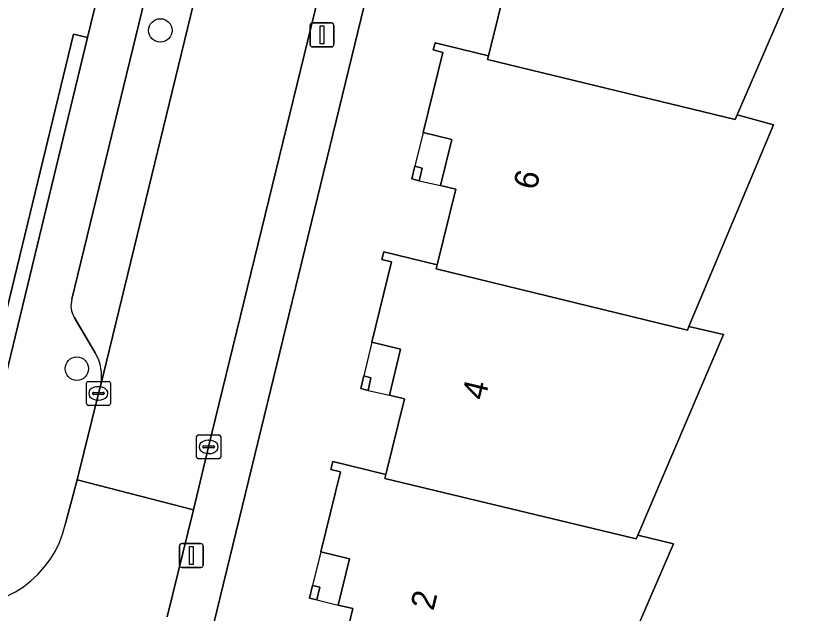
# Model space of a CAD drawing. Extents: x 163266 to 164362, y 381528 to 382286.
# Drawn here: x 164033.14 to 164065.88, y 382076.29 to 382101.22 of the extents above; entities that cross this region are included whole.
import ezdxf

# ---------------------------------------------------------------- set-up
doc = ezdxf.new("R2010")
doc.units = 0
for name, color, linetype in [('IMGEO_Boom', 7, 'Continuous'), ('IMGEO_Erf', 7, 'Continuous'), ('IMGEO_Groenvoorziening', 7, 'Continuous'), ('IMGEO_Haag', 7, 'Continuous'), ('IMGEO_Kolk', 7, 'Continuous'), ('IMGEO_Lichtmast', 7, 'Continuous'), ('IMGEO_Pand', 7, 'Continuous'), ('IMGEO_Pand_nummerreeks', 7, 'Continuous'), ('IMGEO_Pand_overbouw', 7, 'Continuous'), ('IMGEO_Parkeervlak_open', 7, 'Continuous'), ('IMGEO_Rijbaan_lokaal_open', 7, 'Continuous'), ('IMGEO_Voetpad_open', 7, 'Continuous')]:
    doc.layers.add(name, color=color, linetype=linetype)

msp = doc.modelspace()

# ---------------------------------------------------------------- linework, layer by layer
at = {"layer": 'IMGEO_Boom'}
for centre in [(164039.169, 382100.607), (164035.69, 382086.497)]:
    msp.add_circle(centre, 0.489, dxfattribs=at)
at = {"layer": 'IMGEO_Erf'}
for points in [[(164055.615, 382134.307), (164041.028, 382074.335), (164056.155, 382068.998), (164066.938, 382065.194), (164076.002, 382063.011), (164076.035, 382063.211), (164076.111, 382063.521), (164077.023, 382063.297), (164078.096, 382067.688), (164077.183, 382067.911), (164078.503, 382073.312), (164079.825, 382078.723), (164080.737, 382078.499), (164081.848, 382083.048), (164082.961, 382087.602), (164082.048, 382087.825), (164083.378, 382093.267), (164084.719, 382098.754), (164085.631, 382098.53), (164086.738, 382103.06)], [(164066.802, 382105.412), (164063.201, 382097.083), (164064.72, 382096.672), (164061.198, 382088.256), (164062.634, 382087.923), (164059.062, 382079.546), (164060.552, 382079.184), (164056.298, 382069.343), (164052.914, 382070.819)], [(164046.358, 382073.031), (164047.197, 382076.489), (164046.586, 382076.638), (164047.052, 382078.561), (164045.858, 382078.851), (164046.672, 382082.193), (164046.275, 382082.296), (164046.362, 382082.629), (164048.565, 382082.088), (164049.347, 382085.239), (164048.716, 382085.391), (164049.178, 382087.314), (164047.988, 382087.606), (164048.802, 382090.948), (164048.405, 382091.051), (164048.489, 382091.372), (164050.7, 382090.829), (164051.482, 382093.98), (164050.851, 382094.132), (164051.313, 382096.055), (164050.123, 382096.347), (164050.937, 382099.689), (164050.54, 382099.792), (164050.618, 382100.093), (164052.842, 382099.547), (164053.625, 382102.698)]]:
    msp.add_lwpolyline(points, dxfattribs=at)
for points in [[(164049.959, 382094.336), (164049.654, 382094.411), (164049.774, 382094.938), (164050.079, 382094.863)], [(164047.523, 382085.667), (164047.643, 382086.194), (164047.948, 382086.119), (164047.828, 382085.592)], [(164045.695, 382076.855), (164045.39, 382076.93), (164045.51, 382077.457), (164045.815, 382077.382)]]:
    msp.add_lwpolyline(points, close=True, dxfattribs=at)
at = {"layer": 'IMGEO_Groenvoorziening'}
msp.add_lwpolyline([(164022.886, 382088.082), (164031.276, 382082.812), (164035.554, 382100.455), (164036.138, 382100.312), (164036.608, 382102.251), (164036.024, 382102.399), (164042.415, 382128.743), (164042.999, 382128.602), (164046.57, 382143.324), (164043.085, 382144.179), (164040.57, 382144.799), (164040.399, 382144.108), (164040.29, 382143.669), (164044.324, 382142.632), (164041.179, 382131.271)], dxfattribs=at)
msp.add_lwpolyline([(164036.138, 382100.312), (164035.554, 382100.455), (164031.276, 382082.812), (164031.812, 382082.475)], close=True, dxfattribs=at)
at = {"layer": 'IMGEO_Haag'}
msp.add_lwpolyline([(164036.138, 382100.312), (164035.554, 382100.455), (164031.276, 382082.812), (164031.812, 382082.475)], close=True, dxfattribs=at)
at = {"layer": 'IMGEO_Kolk'}
for p, q in [((164036.086, 382085.04), (164036.086, 382085.892)), ((164036.161, 382085.966), (164037.013, 382085.966)), ((164036.574, 382085.746), (164036.599, 382085.746)), ((164037.087, 382085.892), (164037.087, 382085.04)), ((164036.345, 382085.46), (164036.345, 382085.472)), ((164036.783, 382085.423), (164036.385, 382085.423)), ((164036.388, 382085.509), (164036.786, 382085.509)), ((164036.829, 382085.472), (164036.829, 382085.46)), ((164036.597, 382085.186), (164036.572, 382085.186)), ((164037.013, 382084.966), (164036.161, 382084.966)), ((164040.758, 382083.735), (164041.61, 382083.735)), ((164040.683, 382082.809), (164040.683, 382083.661)), ((164041.171, 382083.515), (164041.196, 382083.515)), ((164041.684, 382083.661), (164041.684, 382082.809)), ((164040.942, 382083.229), (164040.942, 382083.241)), ((164041.38, 382083.192), (164040.982, 382083.192)), ((164040.985, 382083.278), (164041.383, 382083.278)), ((164041.426, 382083.241), (164041.426, 382083.229)), ((164041.194, 382082.955), (164041.169, 382082.955)), ((164041.61, 382082.735), (164040.758, 382082.735))]:
    msp.add_line(p, q, dxfattribs=at)
for points in [[(164036.086, 382085.04), (164036.086, 382085.892)], [(164036.161, 382085.966), (164037.013, 382085.966)], [(164037.087, 382085.892), (164037.087, 382085.04)], [(164037.013, 382084.966), (164036.161, 382084.966)], [(164040.758, 382083.735), (164041.61, 382083.735)], [(164040.683, 382082.809), (164040.683, 382083.661)], [(164041.684, 382083.661), (164041.684, 382082.809)], [(164041.61, 382082.735), (164040.758, 382082.735)]]:
    msp.add_lwpolyline(points, dxfattribs=at)
for centre, radius, start, end in [((164036.163, 382085.89), 0.0765, 91.552, 178.448), ((164036.163, 382085.89), 0.0765, 91.552, 178.448), ((164037.011, 382085.89), 0.0765, 1.552, 88.448), ((164037.011, 382085.89), 0.0765, 1.552, 88.448), ((164036.385, 382085.469), 0.0403, 85.8775, 175.7526), ((164036.382, 382085.459), 0.0366, 178.938, 274.7102), ((164036.786, 382085.466), 0.043, 264.8664, 352.4533), ((164036.79, 382085.471), 0.0386, 1.7309, 96.639), ((164036.163, 382085.042), 0.0765, 181.552, 268.448), ((164036.163, 382085.042), 0.0765, 181.552, 268.448), ((164037.011, 382085.042), 0.0765, 271.552, 358.448), ((164037.011, 382085.042), 0.0765, 271.552, 358.448), ((164040.76, 382083.659), 0.0765, 91.552, 178.448), ((164040.76, 382083.659), 0.0765, 91.552, 178.448), ((164041.608, 382083.659), 0.0765, 1.552, 88.448), ((164041.608, 382083.659), 0.0765, 1.552, 88.448), ((164040.982, 382083.238), 0.0403, 85.8775, 175.7526), ((164040.979, 382083.228), 0.0366, 178.938, 274.7102), ((164041.383, 382083.235), 0.043, 264.8664, 352.4533), ((164041.387, 382083.24), 0.0386, 1.7309, 96.639), ((164040.76, 382082.811), 0.0765, 181.552, 268.448), ((164040.76, 382082.811), 0.0765, 181.552, 268.448), ((164041.608, 382082.811), 0.0765, 271.552, 358.448), ((164041.608, 382082.811), 0.0765, 271.552, 358.448)]:
    msp.add_arc(centre, radius, start, end, dxfattribs=at)
for centre, major_axis, ratio, start_param, end_param in [((164036.573, 382085.466), (-0.387, 0.002), 0.722429, 4.712389, 7.853982), ((164036.598, 382085.466), (-0.39, 0.002), 0.717154, 1.570796, 4.712389), ((164041.17, 382083.235), (-0.387, 0.002), 0.722429, 4.712389, 7.853982), ((164041.195, 382083.235), (-0.39, 0.002), 0.717154, 1.570796, 4.712389)]:
    msp.add_ellipse(centre, major_axis=major_axis, ratio=ratio, start_param=start_param, end_param=end_param, dxfattribs=at)
at = {"layer": 'IMGEO_Lichtmast'}
for p, q in [((164045.409, 382100.018), (164045.409, 382100.818)), ((164045.409, 382100.818), (164045.409, 382100.018)), ((164045.509, 382100.918), (164046.299, 382100.918)), ((164046.299, 382100.918), (164045.509, 382100.918)), ((164046.399, 382100.818), (164046.399, 382100.018)), ((164046.399, 382100.018), (164046.399, 382100.818)), ((164046.299, 382099.918), (164045.509, 382099.918)), ((164045.509, 382099.918), (164046.299, 382099.918)), ((164040.064, 382079.202), (164040.854, 382079.202)), ((164040.854, 382079.202), (164040.064, 382079.202)), ((164039.964, 382078.302), (164039.964, 382079.102)), ((164039.964, 382079.102), (164039.964, 382078.302)), ((164040.954, 382079.102), (164040.954, 382078.302)), ((164040.954, 382078.302), (164040.954, 382079.102)), ((164040.854, 382078.202), (164040.064, 382078.202)), ((164040.064, 382078.202), (164040.854, 382078.202))]:
    msp.add_line(p, q, dxfattribs=at)
for points in [[(164045.829, 382100.793), (164045.979, 382100.793), (164045.979, 382100.043), (164045.829, 382100.043), (164045.829, 382100.793)], [(164040.384, 382079.077), (164040.534, 382079.077), (164040.534, 382078.327), (164040.384, 382078.327), (164040.384, 382079.077)]]:
    msp.add_lwpolyline(points, dxfattribs=at)
for centre, start, end in [((164045.509, 382100.818), 90, 180), ((164045.509, 382100.818), 90, 180), ((164046.299, 382100.818), 0, 90), ((164046.299, 382100.818), 360, 90), ((164045.509, 382100.018), 180, 270), ((164045.509, 382100.018), 180, 270), ((164046.299, 382100.018), 270, 0), ((164046.299, 382100.018), 270, 0), ((164040.064, 382079.102), 90, 180), ((164040.064, 382079.102), 90, 180), ((164040.854, 382079.102), 0, 90), ((164040.854, 382079.102), 360, 90), ((164040.064, 382078.302), 180, 270), ((164040.064, 382078.302), 180, 270), ((164040.854, 382078.302), 270, 0), ((164040.854, 382078.302), 270, 0)]:
    msp.add_arc(centre, 0.1, start, end, dxfattribs=at)
at = {"layer": 'IMGEO_Pand'}
for points in [[(164066.802, 382105.412), (164065.293, 382105.846), (164065.199, 382105.63), (164054.923, 382108.148), (164054.962, 382108.305), (164052.755, 382108.847), (164052.674, 382108.538), (164053.071, 382108.435), (164052.251, 382105.068), (164053.455, 382104.772), (164052.993, 382102.85), (164053.625, 382102.698), (164052.842, 382099.547), (164052.804, 382099.396), (164063.118, 382096.892), (164063.201, 382097.083)], [(164064.72, 382096.672), (164063.201, 382097.083), (164063.118, 382096.892), (164052.804, 382099.396), (164052.842, 382099.547), (164050.618, 382100.093), (164050.54, 382099.792), (164050.937, 382099.689), (164050.123, 382096.347), (164051.313, 382096.055), (164050.851, 382094.132), (164051.482, 382093.98), (164050.7, 382090.829), (164050.659, 382090.663), (164061.134, 382088.109), (164061.198, 382088.256)], [(164050.079, 382094.863), (164049.774, 382094.938), (164049.654, 382094.411), (164049.959, 382094.336)], [(164050.7, 382090.829), (164048.489, 382091.372), (164048.405, 382091.051), (164048.802, 382090.948), (164047.988, 382087.606), (164049.178, 382087.314), (164048.716, 382085.391), (164049.347, 382085.239), (164048.565, 382082.088), (164048.522, 382081.917), (164058.996, 382079.398), (164059.062, 382079.546), (164062.634, 382087.923), (164061.198, 382088.256), (164061.134, 382088.109), (164050.659, 382090.663)], [(164047.643, 382086.194), (164047.523, 382085.667), (164047.828, 382085.592), (164047.948, 382086.119)], [(164048.565, 382082.088), (164046.362, 382082.629), (164046.275, 382082.296), (164046.672, 382082.193), (164045.858, 382078.851), (164047.052, 382078.561), (164046.586, 382076.638), (164047.197, 382076.489), (164046.358, 382073.031), (164053.052, 382071.388), (164052.914, 382070.819), (164056.298, 382069.343), (164060.552, 382079.184), (164059.062, 382079.546), (164058.996, 382079.398), (164048.522, 382081.917)], [(164045.695, 382076.855), (164045.815, 382077.382), (164045.51, 382077.457), (164045.39, 382076.93)]]:
    msp.add_lwpolyline(points, close=True, dxfattribs=at)
at = {"layer": 'IMGEO_Pand_overbouw'}
for points in [[(164049.959, 382094.336), (164050.851, 382094.132), (164051.313, 382096.055), (164050.123, 382096.347), (164049.774, 382094.938), (164050.079, 382094.863)], [(164047.643, 382086.194), (164047.948, 382086.119), (164047.828, 382085.592), (164048.716, 382085.391), (164049.178, 382087.314), (164047.988, 382087.606)], [(164045.695, 382076.855), (164046.586, 382076.638), (164047.052, 382078.561), (164045.858, 382078.851), (164045.51, 382077.457), (164045.815, 382077.382)]]:
    msp.add_lwpolyline(points, close=True, dxfattribs=at)
at = {"layer": 'IMGEO_Parkeervlak_open'}
for points in [[(164047.537, 382139.011), (164035.485, 382089.4)], [(164036.687, 382085.824), (164041.679, 382106.359), (164046.97, 382128.236)], [(164035.581, 382088.639), (164036.457, 382087.16)]]:
    msp.add_lwpolyline(points, dxfattribs=at)
for centre, radius, start, end in [((164036.397, 382089.129), 0.952, 163.4283, 210.9515), ((164034.834, 382086.193), 1.889, 348.7456, 30.7905)]:
    msp.add_arc(centre, radius, start, end, dxfattribs=at)
at = {"layer": 'IMGEO_Rijbaan_lokaal_open'}
msp.add_lwpolyline([(164052.625, 382151.386), (164052.524, 382151.033), (164050.518, 382142.784), (164050.296, 382141.81), (164046.97, 382128.236), (164041.679, 382106.359), (164036.687, 382085.824), (164036.649, 382085.666), (164036.588, 382085.465), (164035.703, 382081.86), (164040.553, 382080.61), (164041.183, 382083.235), (164046.634, 382105.618), (164051.259, 382124.564), (164057.77, 382151.298), (164061.553, 382166.894), (164062.081, 382169.185), (164057.256, 382170.333), (164057.165, 382170.006), (164057.135, 382169.884), (164056.44, 382167.012)], close=True, dxfattribs=at)
msp.add_lwpolyline([(164039.454, 382076.15), (164040.553, 382080.61), (164035.703, 382081.86), (164035.221, 382080.033)], dxfattribs=at)
msp.add_arc((164030.921, 382081.002), 4.407, 263.1279, 347.3027, dxfattribs=at)
at = {"layer": 'IMGEO_Voetpad_open'}
for points in [[(164053.773, 382172.715), (164048.04, 382149.326), (164049.998, 382148.86), (164048.546, 382142.852), (164046.57, 382143.324), (164042.999, 382128.602), (164036.608, 382102.251), (164036.138, 382100.312), (164031.812, 382082.475), (164031.336, 382080.636), (164030.394, 382076.626)], [(164062.564, 382171.012), (164062.081, 382169.185), (164061.553, 382166.894), (164057.77, 382151.298), (164051.259, 382124.564), (164046.634, 382105.618), (164041.183, 382083.235), (164040.553, 382080.61), (164039.454, 382076.15)], [(164040.427, 382071.809), (164040.92, 382073.882), (164041.028, 382074.335), (164055.615, 382134.307), (164064.396, 382170.281)], [(164035.485, 382089.4), (164047.537, 382139.011)], [(164036.457, 382087.16), (164035.581, 382088.639)], [(164036.588, 382085.465), (164036.649, 382085.666), (164036.687, 382085.824)], [(164035.221, 382080.033), (164035.703, 382081.86), (164036.588, 382085.465)]]:
    msp.add_lwpolyline(points, dxfattribs=at)
for centre, radius, start, end in [((164036.397, 382089.129), 0.952, 163.4283, 210.9515), ((164034.834, 382086.193), 1.889, 348.7456, 30.7905), ((164030.921, 382081.002), 4.407, 263.1279, 347.3027)]:
    msp.add_arc(centre, radius, start, end, dxfattribs=at)

# ---------------------------------------------------------------- texts
at = {"layer": 'IMGEO_Pand_nummerreeks'}
for s, rotation, p in [('6', 76.2779, (164054.834, 382093.91)), ('4', 76.2773, (164052.691, 382085.14)), ('2', 76.2773, (164050.549, 382076.369))]:
    msp.add_text(s, height=1, rotation=rotation, dxfattribs=at).set_placement(p)

doc.saveas('drawing.dxf')
